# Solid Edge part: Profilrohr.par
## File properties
Username: bmolnar
Dokumentum tartalom típus: 0
Author: bmolnar
Last saved by: bmolnar
Revision: 83
Sűrűség: 0,000 kg/m^3
Pontosság: 0,990
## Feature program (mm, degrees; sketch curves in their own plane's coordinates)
base feature "unnamed BaseFeature 1"
thread "unnamed Thread 1"
thread "Menet_2"  ThreadDepth = 6 mm
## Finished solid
Body 1: solid body, 157 faces, 388 edges, 253 vertices.
  Faces by surface: plane 102, cylinder 41, cone 8, torus 6
  Edges by curve: line 284, circle 92, curve on surface 7, spline 4, intersection 1
Bounding box of the edges (mm; curved faces can reach further): 55.000 x 58.000 x 69.500, from (-27.5, -27.5, 0) to (27.5, 30.5, 69.5).
Cylindrical faces by radius (mm): R1.125 x2, R2.9 x8, R4.283 x4, R4.4 x16, R20 x1, R20.85 x2, R21.1 x2, R22.35 x2, R36.5 x4
Conical faces (half-angle, radius in mm at the cone's reference point): 30 deg R20.325 x2, 45 deg R4.783 x2, 45 deg R21.1 x2, 45 deg R21.35 x2
Toroidal faces (ring radius, tube radius in mm): R20.75 r0.1 x2, R22.15 r0.2 x4
Planar faces by outward normal: +x 9, +y 11, +z 8, -x 9, -y 9, -z 8, oblique 48
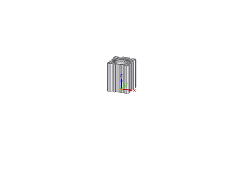
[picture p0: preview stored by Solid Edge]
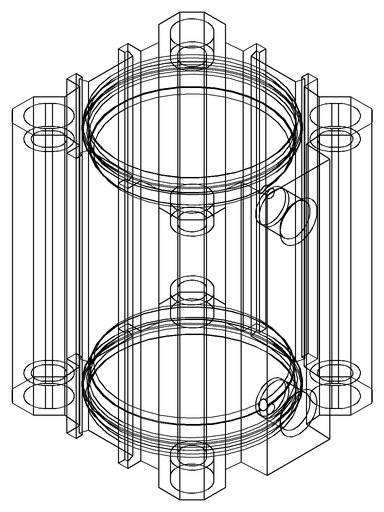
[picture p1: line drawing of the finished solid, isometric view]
